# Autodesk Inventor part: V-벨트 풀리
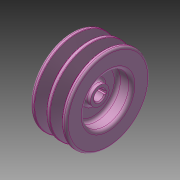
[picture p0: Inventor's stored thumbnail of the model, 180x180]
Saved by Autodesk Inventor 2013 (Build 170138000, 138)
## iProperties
Created: 2024-01
Part Number: V-벨트 풀리
Material: 강철, 주조
Document SubType Name: Modeling
Designer: mdu-01
Density: 1 g/cm^3
Author: mdu-01
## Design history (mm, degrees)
sketch "스케치1"
  geometry: L1 (-9.5, 0)-(9.5, 0); L2 (-9.5, 6)-(-9.5, 9); L3 (-9.5, 9)-(-6.5, 9); L4 (-3.5, 12)-(-3.5, 20); L5 (-6.5, 23)-(-14.5, 23); L6 (-17.5, 26)-(-17.5, 38.5); L7 (0, 0)-(0, 40.5); L8 (9.5, 9)-(6.5, 9); L9 (9.5, 6)-(9.5, 9); L10 (3.5, 12)-(3.5, 20); L11 (6.5, 23)-(14.5, 23); L12 (17.5, 26)-(17.5, 38.5); L13 (-8.5, 5)-(8.5, 5); L14 (-9.5, 6)-(-8.5, 5); L15 (9.5, 6)-(8.5, 5); L16 (-7.5, 40.5)-(-7.5, 28); L17 (-13.368, 40.146)-(-9.87, 28.708); L18 (-1.632, 40.146)-(-5.13, 28.708); L19 (-8.914, 28)-(-6.086, 28); L20 (-15.5, 40.5)-(-13.846, 40.5); L21 (8.914, 28)-(6.086, 28); L22 (1.632, 40.146)-(5.13, 28.708); L23 (13.368, 40.146)-(9.87, 28.708); L24 (-1.154, 40.5)-(1.154, 40.5); L25 (13.846, 40.5)-(15.5, 40.5); A1 r 3 centre (-6.5, 12) between (-6.5, 9) and (-3.5, 12); A2 r 3 centre (-6.5, 20) between (-3.5, 20) and (-6.5, 23); A3 r 3 centre (-14.5, 26) between (-17.5, 26) and (-14.5, 23); A4 r 2 centre (-15.5, 38.5) between (-15.5, 40.5) and (-17.5, 38.5); A5 r 3 centre (6.5, 12) between (3.5, 12) and (6.5, 9); A6 r 3 centre (6.5, 20) between (6.5, 23) and (3.5, 20); A7 r 2 centre (15.5, 38.5) between (17.5, 38.5) and (15.5, 40.5); A8 r 3 centre (14.5, 26) between (14.5, 23) and (17.5, 26); A9 r 1 centre (-8.914, 29) between (-9.87, 28.708) and (-8.914, 28); A10 r 1 centre (-6.086, 29) between (-6.086, 28) and (-5.13, 28.708); A11 r 0.5 centre (-13.846, 40) between (-13.368, 40.146) and (-13.846, 40.5); A12 r 0.5 centre (-1.154, 40) between (-1.154, 40.5) and (-1.632, 40.146); A13 r 0.5 centre (1.154, 40) between (1.632, 40.146) and (1.154, 40.5); A14 r 1 centre (6.086, 29) between (5.13, 28.708) and (6.086, 28); A15 r 1 centre (8.914, 29) between (8.914, 28) and (9.87, 28.708); A16 r 0.5 centre (13.846, 40) between (13.846, 40.5) and (13.368, 40.146); 12 further points
  constraints: 50 end point, 32 point on circle, 32 symmetric about line, 19 point on line, 19 tangent, 16 centre point, 8 perpendicular, 6 parallel, 4 equal radius, 3 midpoint, 1 coincident, 1 horizontal, 8 other
  dimensions: "d0" = 19 distance of L1.start L1.end; "d1" = 3 radius of A1; "d2" = 2 radius of A4; "d3" = 18 diameter of L3 L1; "d4" = 10 diameter of L13 L1; "d5" = 1 distance of L2.start point (-9.5, 5); "d6" = 1 distance of L13.start point (-9.5, 5) (= d5); "d7" = 1 distance of L9.start point (9.5, 5) (= d5); "d8" = 1 distance of L13.end point (9.5, 5) (= d7); "d9" = 7 distance between parallel lines of L10 L4; "d10" = 46 diameter of L5 L1; "d11" = 35 distance between parallel lines of L12 L6; "d13" = 72 diameter of point (-12.1, 36) L1; "d14" = 34 deg angle of L18 L17; "d15" = 9.2 diameter of point (-12.1, 36) L16; "d16" = 15 diameter of L16 L7; "d17" = 8 distance from line of L19 point (-12.1, 36); "d18" = 4.5 distance from line of L20 point (-12.1, 36); "d19" = 1 radius of A9; "d20" = 0.5 radius of A11
revolve "회전1" sketch "스케치1" stored, may be unused: angle "d21" = 90 deg
sketch "스케치2"
  geometry: L1 (-1.5, 4.77)-(1.5, 4.77); L2 (1.5, 4.77)-(1.5, 6.4); L3 (1.5, 6.4)-(-1.5, 6.4); L4 (-1.5, 6.4)-(-1.5, 4.77); A1 r 5 centre (0, 0) between (-1.5, 4.77) and (1.5, 4.77) reference; 2 further points
  constraints: 8 end point, 3 point on circle, 2 parallel, 1 horizontal, 1 perpendicular, 1 vertical alignment
  dimensions: "d22" = 3 distance between parallel lines of L2 L4; "d24" = 11.4 distance from line of point (0, -5) L3
extrude "돌출1" cut sketch "스케치2" stored distance "d25" = 10; taper "d26" = 0 deg
node "솔리드1"
other parameters: "d12" = 81
